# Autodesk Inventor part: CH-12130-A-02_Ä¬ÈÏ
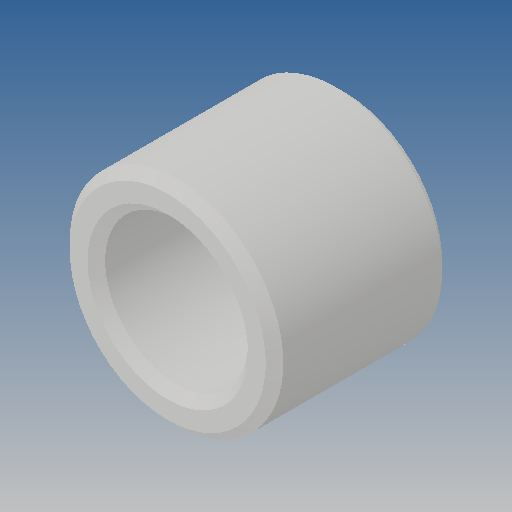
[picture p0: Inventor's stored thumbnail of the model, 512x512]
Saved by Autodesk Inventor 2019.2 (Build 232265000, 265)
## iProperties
Created: 2010-06
Part Number: CH-12130-A-02_Ä¬ÈÏ
Material: Ogólny
Document SubType Name: Modeling
Designer: CADENGINEERING4
Density: 1 g/cm^3
Appearance: Domyślna
Author: CADENGINEERING4
Revision Number: ÈÎºÎ
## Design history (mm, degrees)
feature "NONE"
node "Bryła1"
